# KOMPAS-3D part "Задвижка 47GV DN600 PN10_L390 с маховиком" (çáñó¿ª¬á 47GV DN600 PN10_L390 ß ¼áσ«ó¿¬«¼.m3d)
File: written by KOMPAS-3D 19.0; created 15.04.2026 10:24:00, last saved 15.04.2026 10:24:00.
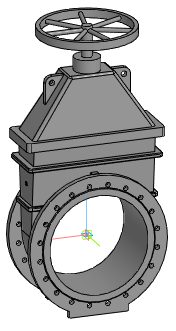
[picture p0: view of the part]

Document properties: Автор: Евгений; Полное имя файла: Z:\3.Личные\kachalov\3d для проектировщиков\2.1 Тип 47GV, 47GV.Z\Задвижка 47GV_DN40-DN600\stp_Задвижка 47GV\Задвижка 47GV DN600 PN10_L390 с маховиком.m3d

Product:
- Part/product: Задвижка 47GV DN600 PN10_L390 с маховиком

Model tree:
1. Операция без истории:1  (labels: Задвижка 47GV DN600 PN10_L390 с маховиком)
